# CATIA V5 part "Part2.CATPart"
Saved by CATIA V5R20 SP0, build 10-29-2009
Part number: Part2
Bounding box of the stored display mesh (mm): x 28 to 70, y 270 to 300, z 40.953 to 65.953
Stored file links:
  E:\Ehsan\CATIA\Tamrin\Digital Mockup\3\Part2.CATPart
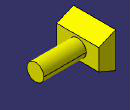
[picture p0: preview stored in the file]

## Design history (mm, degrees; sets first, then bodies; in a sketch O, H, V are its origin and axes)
Body1 (main body)
  DatumSurface1 to DatumSurface3
  Sketch1 on face of DatumSurface1, origin (0, 300, 0), H (1, 0, 0), V (0, 0, 1)
  Pad1: profile Sketch1, direction (0, -1, 0), length 30
  Sketch2 on face of Pad1, origin (40, 0, 0), H (0, 1, 0), V (0, 0, 1)
    circle A1 centre (285, 53.4531) radius 6
    point P1 (285, 53.4531)
    reference projected line E1 (270, 45.9531) -> (270, 60.9531) from edge [face of Pad1 | end face of Pad1]
    reference projected line E2 (300, 45.9531) -> (270, 45.9531) from edge [face of Pad1 | face of Pad1]
    radius A1 = 6
    distance P1 E1 = 15
    distance P1 E2 = 7.5
  Pad2: profile Sketch2, direction (1, 0, 0), length 30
